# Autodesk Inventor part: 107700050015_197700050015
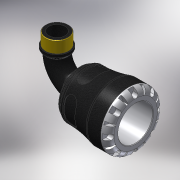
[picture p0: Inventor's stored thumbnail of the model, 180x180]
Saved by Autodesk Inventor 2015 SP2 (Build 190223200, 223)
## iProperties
Created: 2016-12
Part Number: 107700050015_197700050015
Material: PVC-Piping
Description: PLASSON 90° ELBOW WITH MALE INTEGRAL BRASS 50X1.1/2" SERIES 1
Document SubType Name: Modeling
Designer: KIM
Mass: 664.223 g
Surface Area: 733.008 cm^2
Volume: 474.445 cm^3
Density: 1.4 g/cm^3
Appearance: Black Cast
Author: KIM
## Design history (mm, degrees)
derived "1077.ipt"
feature "Solid1::1077.ipt"
tag "TaggingFeature1"
body "Solid1"
other parameters: "d1" = 33.18, "d3" = 62.5, "d4" = 85, "d8" = 72.25, "d13" = 9, "d14" = 9, "d15" = 0, "d17" = 360 deg, "d19" = 8 deg, "d20" = 1, "d21" = 1, "d22" = 8 deg, "d24" = 0, "d26" = 360 deg, "d33" = 8.5, "d43" = 66.3, "d51" = 0.85, "d54" = 17.5, "d55" = 11, "d57" = 17.64, "d58" = 0, "d74" = 0, "d78" = 79, "d82" = 1, "d115" = 360 deg, "d207" = 90 deg, "d228" = 14.875, "d247" = 1.7, "d248" = 4.74, "d268" = 39.7375, "d269" = 4.74, "d270" = 116, "d276" = 47.803, "d277" = 21, "d278" = 52.5833, "d279" = 73, "d280" = 27.3, "d281" = 7.17045, "d283" = 43.0227, "d286" = 0, "d287" = 0, "d288" = 33.4621, "d290" = 11.63865, "d292" = 30 deg, "d294" = 4.7803, "d296" = 30 deg, "E_" = 85, "l_" = 79, "A_" = 116, "A_1" = 73, "l_2" = 21, "R_" = 47.803, "d9" = 11.25, "d11" = 85, "d12" = 62.5, "d289" = 33.4621
